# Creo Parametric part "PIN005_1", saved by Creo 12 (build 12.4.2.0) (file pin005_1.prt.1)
Units: Custom; MM, KILOGRAM, SECS

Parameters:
  PTC_WM_ITERATION = "0"
  PTC_WM_VERSION = "-.0"
  PTC_WM_LIFECYCLE_STATE = "In Work"
  PTC_WM_LIFECYCLE = "MO_CADDocument"
  PTC_WM_CREATED_BY = "Maximilian Roepper (Z0017RMS: MO)"
  PTC_WM_CREATED_ON = "18-Sep-26 11:36:42 AM"
  PTC_WM_MODIFIED_BY = "Maximilian Roepper (Z0017RMS: MO)"
  PTC_WM_MODIFIED_ON = "18-Sep-26 11:36:46 AM"
  PDMLINKNUMBER = "PDM000071455291"
  PTC_WM_NAME = "pin005_1.prt"
  PTC_WM_NUMBER = "PDM000071455291"

Other parameters: WEIGHT, WEIGHT_FACTOR, WEIGHT_ADD, _MASS_TEMP, _DIFF_TEMP, MC_ERRORS, SUPPLIER

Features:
  1. coordinate system
  2. datum plane "PRT_YZ"
  3. datum plane "PRT_XY"
  4. datum plane "PRT_XZ"
  5. coordinate system
  6. datum axis
  7. datum axis
  8. datum axis
  9. coordinate system
  10. imported feature

Other named items: PRT, SIEMENS_MO, DRW_VIEW_ORG, PRT_X, PRT_Y, PRT_Z, CS0, ROUGH_GROB

Layers: 00_STD_CSYS-KSYS, 01_STD_PLANES-EBENEN, 02_STD_AXES-ACHSEN, 03_STD_CSYS-KSYS, 24_IMPORT_FEAT-IMPORT_KE

Surfaces: 14 plane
